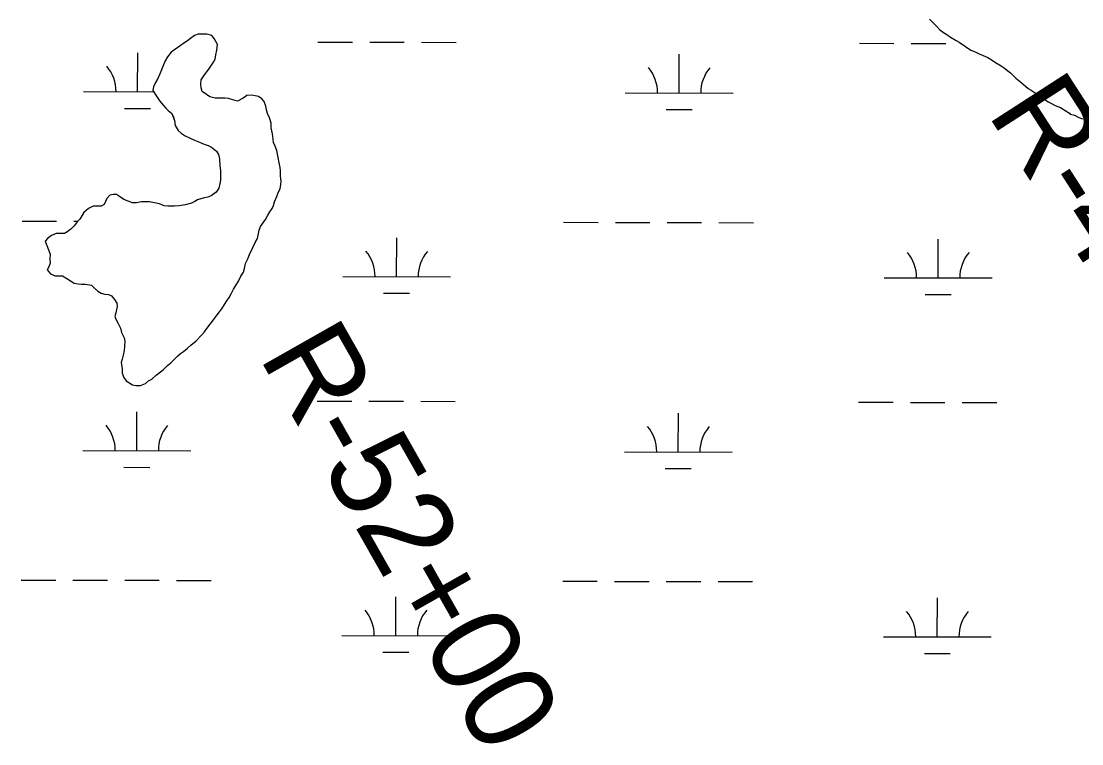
# Model space of a CAD drawing. Extents: x 3180038 to 3217926, y 922069 to 947485.
# Drawn here: x 3193033 to 3194016, y 935833 to 936503 of the extents above; entities that cross this region are included whole.
import ezdxf

# ---------------------------------------------------------------- set-up
doc = ezdxf.new("R2010")
doc.units = 0
for name, color, linetype in [('V-RIVR-RANG-IDEN', 7, 'Continuous'), ('V-SITE-VEGE', 7, 'Continuous'), ('V-TOPO-SHOR', 7, 'Continuous'), ('V-WETL-SWMP', 7, 'Continuous')]:
    doc.layers.add(name, color=color, linetype=linetype)

msp = doc.modelspace()

# ---------------------------------------------------------------- linework, layer by layer
at = {"layer": 'V-SITE-VEGE'}
for points in [[(3193875.23, 936504.62), (3193877.99, 936501.92), (3193881.45, 936498.55), (3193884.91, 936494.83), (3193888.35, 936492.49), (3193891.45, 936490.48), (3193894.9, 936488.13), (3193900.06, 936485.12), (3193902.81, 936483.44), (3193908.67, 936479.42), (3193913.49, 936476.06)], [(3193273.45, 936367.39), (3193272.71, 936371.47), (3193271.63, 936376.58), (3193270.52, 936383.06), (3193268.76, 936387.13), (3193267.35, 936390.53), (3193266.97, 936393.6), (3193266.23, 936398.37), (3193265.14, 936404.17), (3193265.09, 936408.26), (3193263.66, 936413.37), (3193261.9, 936417.44), (3193260.83, 936420.85), (3193260.11, 936424.25), (3193258.69, 936428.33), (3193256.61, 936431.04), (3193253.51, 936433.05), (3193250.43, 936433.7), (3193247, 936434.34), (3193242.57, 936433.94), (3193239.18, 936431.51), (3193234.09, 936428.71), (3193229.64, 936430.02), (3193225.52, 936431.34), (3193222.45, 936431.64), (3193217.32, 936431.58), (3193213.23, 936431.53), (3193208.43, 936432.84), (3193205.33, 936434.84), (3193201.19, 936437.87), (3193200.13, 936441.27), (3193200.09, 936444.34), (3193200.38, 936448.45), (3193203.39, 936453.26), (3193207.43, 936458.44), (3193209.1, 936461.19), (3193211.79, 936464.98), (3193213.12, 936467.73), (3193213.75, 936471.84), (3193214.73, 936475.95), (3193215.34, 936481.42), (3193213.94, 936484.13), (3193212.2, 936486.85), (3193210.12, 936489.55), (3193205.66, 936490.86), (3193201.56, 936490.81), (3193197.47, 936490.76), (3193194.06, 936489.69), (3193190.34, 936486.91), (3193187.64, 936484.83), (3193184.25, 936482.4), (3193180.86, 936479.97), (3193175.44, 936476.48), (3193172.4, 936474.06), (3193169.03, 936469.91), (3193167.03, 936466.13), (3193164.71, 936460.98), (3193162.39, 936454.81), (3193160.06, 936449.65), (3193158.06, 936446.21), (3193156.06, 936442.09), (3193155.42, 936438.67), (3193158.9, 936433.25), (3193162.03, 936428.85), (3193165.5, 936424.79), (3193167.57, 936422.43), (3193169.66, 936420.06), (3193172.75, 936417.71), (3193174.15, 936414.99), (3193175.57, 936410.91), (3193176.32, 936406.14), (3193179.1, 936401.73), (3193181.87, 936399.04), (3193185.31, 936396.69), (3193189.43, 936394.69), (3193194.24, 936392.7), (3193198.7, 936390.71), (3193203.16, 936389.06), (3193206.6, 936387.73), (3193209.69, 936386.06), (3193214.52, 936382.36), (3193216.26, 936379.31), (3193217.34, 936375.23), (3193217.42, 936368.74), (3193218.15, 936364.65), (3193218.21, 936360.21), (3193218.27, 936355.43), (3193217.62, 936352.35), (3193216.65, 936348.24), (3193214.3, 936344.45), (3193209.57, 936340.98), (3193206.5, 936339.92), (3193203.1, 936339.19), (3193196.97, 936337.41), (3193194.26, 936335.67), (3193191.21, 936334.26), (3193185.42, 936332.82), (3193179.97, 936331.73), (3193175.53, 936331.33), (3193169.38, 936331.6), (3193165.96, 936331.9)], [(3193913.49, 936476.06), (3193917.61, 936474.41), (3193921.39, 936472.74), (3193925.16, 936471.08), (3193929.29, 936469.09), (3193933.41, 936466.75), (3193936.51, 936464.74), (3193941.68, 936461.38), (3193944.43, 936459.71), (3193947.88, 936457.02), (3193950.3, 936455), (3193952.71, 936452.98), (3193955.48, 936449.94), (3193959.97, 936446.24), (3193964.45, 936442.54), (3193966.87, 936440.52), (3193969.62, 936438.85), (3193974.1, 936435.83), (3193979.95, 936431.81), (3193985.46, 936428.12), (3193988.9, 936426.45), (3193991.65, 936424.78), (3193996.8, 936422.79), (3194000.93, 936420.11), (3194005.06, 936417.77), (3194005.76, 936416.75), (3194009.86, 936415.78), (3194013.65, 936413.78), (3194017.08, 936412.46)], [(3193060.31, 936286.87), (3193060.02, 936282.77), (3193060.41, 936278.68), (3193059.08, 936275.25), (3193057.41, 936272.5), (3193060.53, 936268.78), (3193064.99, 936266.78), (3193068.07, 936266.82), (3193071.82, 936266.87), (3193075.61, 936264.52), (3193079.05, 936262.18), (3193082.49, 936260.17), (3193086.26, 936259.53), (3193089.34, 936259.23), (3193092.75, 936259.27), (3193098.57, 936258.32), (3193101.34, 936255.62), (3193104.45, 936252.59), (3193107.54, 936250.92), (3193110.97, 936249.93), (3193114.39, 936249.64), (3193117.14, 936248.3), (3193119.91, 936244.92), (3193122, 936241.53), (3193122.38, 936238.46), (3193121.09, 936232.64), (3193120.1, 936229.22), (3193121.51, 936226.16), (3193122.91, 936223.44), (3193125.36, 936218.35), (3193126.44, 936214.27), (3193128.89, 936209.52), (3193129.61, 936206.45), (3193129.33, 936201.33), (3193129.04, 936197.56), (3193128.06, 936193.45), (3193127.08, 936189.68), (3193126.1, 936186.6), (3193127.19, 936180.81), (3193126.9, 936176.7), (3193128.66, 936172.63), (3193130.75, 936169.58), (3193136.6, 936165.9), (3193139.68, 936165.25), (3193144.12, 936165.31), (3193148.54, 936167.07), (3193151.58, 936169.5), (3193154.63, 936171.24), (3193158.69, 936174.71), (3193161.39, 936177.13), (3193165.11, 936179.91), (3193169.17, 936183.72), (3193172.21, 936186.14), (3193175.24, 936189.26), (3193178.62, 936192.71), (3193180.98, 936194.79), (3193184.03, 936196.88), (3193187.75, 936200), (3193190.79, 936202.77), (3193195.52, 936206.58), (3193200.92, 936212.12), (3193203.27, 936214.88), (3193205.63, 936217.98), (3193208.65, 936222.11), (3193211.67, 936226.25), (3193213.69, 936228.67), (3193216.04, 936232.11), (3193219.4, 936236.25), (3193221.74, 936240.38), (3193224.09, 936243.82), (3193226.1, 936246.92), (3193228.11, 936250.36), (3193230.11, 936254.49), (3193232.45, 936257.93), (3193234.79, 936262.05), (3193237.13, 936266.53), (3193239.47, 936270.31), (3193240.45, 936273.74), (3193241.42, 936278.19), (3193243.42, 936282.65), (3193245.07, 936286.77), (3193248.07, 936293.3), (3193250.4, 936297.77), (3193252.4, 936301.55), (3193253.37, 936306), (3193254.02, 936309.09), (3193255.34, 936312.52), (3193260.04, 936319.06), (3193261.71, 936322.5), (3193264.05, 936326.28), (3193266.06, 936329.38), (3193267.39, 936332.13), (3193268.38, 936335.56), (3193270.37, 936340.36), (3193272.02, 936344.82), (3193273.35, 936347.58), (3193273.98, 936351.68), (3193274.29, 936354.76), (3193273.89, 936359.19), (3193273.83, 936364.32), (3193273.45, 936367.39)], [(3193165.96, 936331.9), (3193161.5, 936333.55), (3193155.34, 936334.84), (3193152.26, 936335.49), (3193149.19, 936335.45), (3193145.09, 936335.4), (3193140.31, 936334.66), (3193136.56, 936334.61), (3193128.67, 936337.59), (3193124.53, 936340.27), (3193121.78, 936342.28), (3193118.71, 936342.25), (3193115.64, 936341.52), (3193112.95, 936338.42), (3193111.61, 936335.67), (3193110.28, 936332.92), (3193107.57, 936331.52), (3193103.13, 936331.46), (3193100.05, 936331.42), (3193095.98, 936329.33), (3193091.59, 936325.52), (3193089.58, 936322.42), (3193087.91, 936319.32), (3193085.21, 936316.9), (3193082.52, 936313.11), (3193079.82, 936310.34), (3193076.78, 936307.91), (3193073.73, 936306.17), (3193071.68, 936306.14), (3193069.97, 936306.12), (3193065.87, 936306.07), (3193061.46, 936304.31), (3193057.73, 936301.53), (3193056.05, 936299.46), (3193055.71, 936299.11), (3193060.31, 936286.87)]]:
    msp.add_lwpolyline(points, dxfattribs=at)
at = {"layer": 'V-TOPO-SHOR'}
for points in [[(3193875.23, 936504.62), (3193877.99, 936501.92), (3193881.45, 936498.55), (3193884.91, 936494.83), (3193888.35, 936492.49), (3193891.45, 936490.48), (3193894.9, 936488.13), (3193900.06, 936485.12), (3193902.81, 936483.44), (3193908.67, 936479.42), (3193913.49, 936476.06), (3193917.61, 936474.41), (3193921.39, 936472.74), (3193925.16, 936471.08), (3193929.29, 936469.09), (3193933.41, 936466.75), (3193936.51, 936464.74), (3193941.68, 936461.38), (3193944.43, 936459.71), (3193947.88, 936457.02), (3193950.3, 936455), (3193952.71, 936452.98), (3193955.48, 936449.94), (3193959.97, 936446.24), (3193964.45, 936442.54), (3193966.87, 936440.52), (3193969.62, 936438.85), (3193974.1, 936435.83), (3193979.95, 936431.81), (3193985.46, 936428.12), (3193988.9, 936426.45), (3193991.65, 936424.78), (3193996.8, 936422.79), (3194000.93, 936420.11), (3194005.06, 936417.77), (3194005.76, 936416.75), (3194009.86, 936415.78), (3194013.65, 936413.78), (3194017.08, 936412.46)], [(3193273.45, 936367.39), (3193272.71, 936371.47), (3193271.63, 936376.58), (3193270.52, 936383.06), (3193268.76, 936387.13), (3193267.35, 936390.53), (3193266.97, 936393.6), (3193266.23, 936398.37), (3193265.14, 936404.17), (3193265.09, 936408.26), (3193263.66, 936413.37), (3193261.9, 936417.44), (3193260.83, 936420.85), (3193260.11, 936424.25), (3193258.69, 936428.33), (3193256.61, 936431.04), (3193253.51, 936433.05), (3193250.43, 936433.7), (3193247, 936434.34), (3193242.57, 936433.94), (3193239.18, 936431.51), (3193234.09, 936428.71), (3193229.64, 936430.02), (3193225.52, 936431.34), (3193222.45, 936431.64), (3193217.32, 936431.58), (3193213.23, 936431.53), (3193208.43, 936432.84), (3193205.33, 936434.84), (3193201.19, 936437.87), (3193200.13, 936441.27), (3193200.09, 936444.34), (3193200.38, 936448.45), (3193203.39, 936453.26), (3193207.43, 936458.44), (3193209.1, 936461.19), (3193211.79, 936464.98), (3193213.12, 936467.73), (3193213.75, 936471.84), (3193214.73, 936475.95), (3193215.34, 936481.42), (3193213.94, 936484.13), (3193212.2, 936486.84), (3193210.12, 936489.55), (3193205.66, 936490.86), (3193201.56, 936490.81), (3193197.47, 936490.76), (3193194.06, 936489.69), (3193190.34, 936486.91), (3193187.63, 936484.83), (3193184.25, 936482.4), (3193180.86, 936479.97), (3193175.44, 936476.48), (3193172.4, 936474.06), (3193169.03, 936469.91), (3193167.03, 936466.13), (3193164.71, 936460.98), (3193162.39, 936454.81), (3193160.06, 936449.65), (3193158.06, 936446.21), (3193156.06, 936442.09), (3193155.42, 936438.67), (3193158.9, 936433.25), (3193162.03, 936428.85), (3193165.5, 936424.79), (3193167.57, 936422.43), (3193169.65, 936420.06), (3193172.76, 936417.71), (3193174.15, 936414.99), (3193175.57, 936410.91), (3193176.32, 936406.14), (3193179.1, 936401.73), (3193181.87, 936399.04), (3193185.31, 936396.69), (3193189.43, 936394.69), (3193194.24, 936392.7), (3193198.7, 936390.71), (3193203.16, 936389.06), (3193206.6, 936387.73), (3193209.69, 936386.06), (3193214.52, 936382.36), (3193216.26, 936379.31), (3193217.34, 936375.23), (3193217.42, 936368.74), (3193218.15, 936364.65), (3193218.21, 936360.21), (3193218.27, 936355.43), (3193217.62, 936352.35), (3193216.65, 936348.24), (3193214.3, 936344.45), (3193209.57, 936340.98), (3193206.5, 936339.92), (3193203.1, 936339.19), (3193196.97, 936337.41), (3193194.26, 936335.67), (3193191.21, 936334.26), (3193185.42, 936332.82), (3193179.97, 936331.73), (3193175.53, 936331.33), (3193169.38, 936331.6), (3193165.96, 936331.9)], [(3193060.31, 936286.87), (3193060.02, 936282.77), (3193060.41, 936278.68), (3193059.08, 936275.25), (3193057.41, 936272.5), (3193060.53, 936268.78), (3193064.99, 936266.78), (3193068.07, 936266.82), (3193071.82, 936266.87), (3193075.61, 936264.52), (3193079.05, 936262.18), (3193082.49, 936260.17), (3193086.26, 936259.53), (3193089.34, 936259.23), (3193092.75, 936259.27), (3193098.57, 936258.32), (3193101.33, 936255.62), (3193104.45, 936252.59), (3193107.54, 936250.92), (3193110.97, 936249.93), (3193114.39, 936249.64), (3193117.14, 936248.3), (3193119.91, 936244.92), (3193122, 936241.53), (3193122.38, 936238.46), (3193121.09, 936232.64), (3193120.1, 936229.22), (3193121.51, 936226.16), (3193122.91, 936223.44), (3193125.36, 936218.35), (3193126.44, 936214.27), (3193128.89, 936209.52), (3193129.61, 936206.45), (3193129.33, 936201.33), (3193129.04, 936197.56), (3193128.06, 936193.45), (3193127.08, 936189.68), (3193126.1, 936186.6), (3193127.19, 936180.81), (3193126.9, 936176.7), (3193128.66, 936172.63), (3193130.75, 936169.58), (3193136.6, 936165.9), (3193139.68, 936165.25), (3193144.12, 936165.31), (3193148.54, 936167.07), (3193151.58, 936169.5), (3193154.63, 936171.24), (3193158.69, 936174.71), (3193161.39, 936177.13), (3193165.11, 936179.91), (3193169.17, 936183.72), (3193172.21, 936186.14), (3193175.24, 936189.26), (3193178.62, 936192.71), (3193180.98, 936194.79), (3193184.03, 936196.88), (3193187.75, 936200), (3193190.79, 936202.77), (3193195.52, 936206.58), (3193200.92, 936212.12), (3193203.27, 936214.88), (3193205.63, 936217.98), (3193208.65, 936222.11), (3193211.67, 936226.25), (3193213.69, 936228.67), (3193216.04, 936232.11), (3193219.4, 936236.25), (3193221.74, 936240.38), (3193224.09, 936243.82), (3193226.1, 936246.92), (3193228.11, 936250.36), (3193230.11, 936254.49), (3193232.45, 936257.93), (3193234.79, 936262.06), (3193237.13, 936266.53), (3193239.47, 936270.31), (3193240.45, 936273.74), (3193241.42, 936278.19), (3193243.42, 936282.65), (3193245.07, 936286.77), (3193248.07, 936293.3), (3193250.4, 936297.77), (3193252.4, 936301.55), (3193253.37, 936306), (3193254.02, 936309.08), (3193255.34, 936312.52), (3193260.04, 936319.06), (3193261.71, 936322.5), (3193264.05, 936326.28), (3193266.06, 936329.38), (3193267.39, 936332.13), (3193268.38, 936335.56), (3193270.37, 936340.37), (3193272.02, 936344.82), (3193273.35, 936347.58), (3193273.98, 936351.68), (3193274.29, 936354.76), (3193273.89, 936359.19), (3193273.83, 936364.32), (3193273.45, 936367.39)], [(3193165.96, 936331.9), (3193161.5, 936333.55), (3193155.34, 936334.84), (3193152.26, 936335.49), (3193149.19, 936335.45), (3193145.09, 936335.4), (3193140.31, 936334.66), (3193136.56, 936334.61), (3193128.67, 936337.59), (3193124.53, 936340.27), (3193121.78, 936342.28), (3193118.71, 936342.24), (3193115.64, 936341.52), (3193112.95, 936338.42), (3193111.61, 936335.67), (3193110.28, 936332.92), (3193107.57, 936331.52), (3193103.13, 936331.46), (3193100.05, 936331.42), (3193095.98, 936329.33), (3193091.59, 936325.51), (3193089.58, 936322.42), (3193087.91, 936319.32), (3193085.21, 936316.9), (3193082.52, 936313.11), (3193079.82, 936310.34), (3193076.78, 936307.91), (3193073.73, 936306.17), (3193071.68, 936306.14), (3193069.97, 936306.12), (3193065.87, 936306.07), (3193061.46, 936304.31), (3193057.73, 936301.53), (3193056.05, 936299.46), (3193055.71, 936299.11), (3193060.31, 936286.87)]]:
    msp.add_lwpolyline(points, dxfattribs=at)
at = {"layer": 'V-WETL-SWMP'}
for p, q in [((3193308.51, 936483.55), (3193340.51, 936483.47)), ((3193356.51, 936483.44), (3193388.51, 936483.37)), ((3193404.51, 936483.33), (3193436.51, 936483.26)), ((3193810.42, 936482.41), (3193842.42, 936482.34)), ((3193858.42, 936482.31), (3193890.42, 936482.23)), ((3193141.35, 936437.49), (3193141.43, 936473.49)), ((3193643.25, 936436.36), (3193643.33, 936472.36)), ((3193091.35, 936437.61), (3193156.19, 936437.46)), ((3193593.25, 936436.48), (3193693.25, 936436.25)), ((3193129.31, 936422.09), (3193153.31, 936422.04)), ((3193631.22, 936420.96), (3193655.22, 936420.91)), ((3193034.23, 936317.67), (3193066.23, 936317.6)), ((3193082.23, 936317.56), (3193085.94, 936317.55)), ((3193536.14, 936316.54), (3193568.14, 936316.46)), ((3193584.14, 936316.43), (3193616.14, 936316.36)), ((3193632.13, 936316.32), (3193664.13, 936316.25)), ((3193680.13, 936316.21), (3193712.13, 936316.14)), ((3193381.43, 936266.15), (3193381.51, 936302.14)), ((3193883.33, 936265.01), (3193883.42, 936301.01)), ((3193331.43, 936266.26), (3193431.43, 936266.03)), ((3193833.33, 936265.13), (3193933.33, 936264.9)), ((3193369.39, 936250.74), (3193393.39, 936250.69)), ((3193871.3, 936249.61), (3193895.3, 936249.56)), ((3193307.76, 936150.88), (3193339.76, 936150.81)), ((3193355.76, 936150.77), (3193387.76, 936150.7)), ((3193403.76, 936150.67), (3193435.76, 936150.59)), ((3193809.66, 936149.75), (3193841.66, 936149.68)), ((3193857.66, 936149.64), (3193889.66, 936149.57)), ((3193140.59, 936104.83), (3193140.67, 936140.83)), ((3193905.66, 936149.53), (3193937.66, 936149.46)), ((3193642.5, 936103.7), (3193642.58, 936139.7)), ((3193090.59, 936104.94), (3193190.59, 936104.72)), ((3193592.5, 936103.81), (3193692.5, 936103.59)), ((3193128.56, 936089.43), (3193152.56, 936089.37)), ((3193630.46, 936088.3), (3193654.46, 936088.24)), ((3193033.47, 935985.01), (3193065.47, 935984.93)), ((3193081.47, 935984.9), (3193113.47, 935984.83)), ((3193129.47, 935984.79), (3193161.47, 935984.72)), ((3193177.47, 935984.68), (3193209.47, 935984.61)), ((3193535.38, 935983.87), (3193567.38, 935983.8)), ((3193583.38, 935983.77), (3193615.38, 935983.69)), ((3193631.38, 935983.66), (3193663.38, 935983.59)), ((3193679.38, 935983.55), (3193711.38, 935983.48)), ((3193380.67, 935933.48), (3193380.75, 935969.48)), ((3193882.58, 935932.35), (3193882.66, 935968.35)), ((3193330.67, 935933.59), (3193430.67, 935933.37)), ((3193832.58, 935932.46), (3193932.58, 935932.24)), ((3193368.64, 935918.08), (3193392.64, 935918.02)), ((3193870.54, 935916.95), (3193894.54, 935916.89))]:
    msp.add_line(p, q, dxfattribs=at)
for points in [[(3193875.23, 936504.62), (3193877.99, 936501.92), (3193881.45, 936498.55), (3193884.91, 936494.83), (3193888.35, 936492.49), (3193891.45, 936490.48), (3193894.9, 936488.13), (3193900.06, 936485.12), (3193902.81, 936483.44), (3193908.67, 936479.42), (3193913.49, 936476.06), (3193917.61, 936474.41), (3193921.39, 936472.75), (3193925.16, 936471.08), (3193929.29, 936469.09), (3193933.41, 936466.75), (3193936.51, 936464.74), (3193941.68, 936461.39), (3193944.43, 936459.71), (3193947.88, 936457.02), (3193950.29, 936455), (3193952.71, 936452.98), (3193955.48, 936449.94), (3193959.97, 936446.24), (3193964.45, 936442.54), (3193966.87, 936440.52), (3193969.62, 936438.85), (3193974.1, 936435.83), (3193979.95, 936431.8), (3193985.46, 936428.12), (3193988.9, 936426.45), (3193991.65, 936424.78), (3193996.8, 936422.79), (3194000.93, 936420.11), (3194005.06, 936417.77), (3194005.75, 936416.76), (3194009.86, 936415.78), (3194013.65, 936413.78), (3194017.08, 936412.46)], [(3193273.45, 936367.38), (3193272.71, 936371.47), (3193271.63, 936376.58), (3193270.52, 936383.06), (3193268.76, 936387.13), (3193267.35, 936390.53), (3193266.97, 936393.6), (3193266.23, 936398.37), (3193265.14, 936404.17), (3193265.09, 936408.26), (3193263.66, 936413.37), (3193261.9, 936417.45), (3193260.83, 936420.85), (3193260.11, 936424.25), (3193258.69, 936428.33), (3193256.61, 936431.04), (3193253.51, 936433.05), (3193250.43, 936433.7), (3193247, 936434.34), (3193242.57, 936433.94), (3193239.18, 936431.51), (3193234.09, 936428.71), (3193229.64, 936430.02), (3193225.52, 936431.34), (3193222.45, 936431.64), (3193217.32, 936431.58), (3193213.23, 936431.53), (3193208.43, 936432.84), (3193205.33, 936434.85), (3193201.19, 936437.87), (3193200.13, 936441.27), (3193200.09, 936444.34), (3193200.38, 936448.45), (3193203.39, 936453.26), (3193207.43, 936458.44), (3193209.1, 936461.19), (3193211.79, 936464.98), (3193213.12, 936467.73), (3193213.75, 936471.84), (3193214.73, 936475.95), (3193215.34, 936481.42), (3193213.94, 936484.13), (3193212.2, 936486.84), (3193210.12, 936489.55), (3193205.66, 936490.86), (3193201.56, 936490.81), (3193197.47, 936490.76), (3193194.06, 936489.69), (3193190.34, 936486.91), (3193187.63, 936484.83), (3193184.25, 936482.4), (3193180.86, 936479.97), (3193175.44, 936476.48), (3193172.4, 936474.06), (3193169.04, 936469.92), (3193167.03, 936466.13), (3193164.71, 936460.98), (3193162.39, 936454.81), (3193160.06, 936449.65), (3193158.06, 936446.21), (3193156.06, 936442.09), (3193155.42, 936438.67), (3193158.9, 936433.25), (3193162.03, 936428.85), (3193165.5, 936424.79), (3193167.57, 936422.42), (3193169.65, 936420.06), (3193172.76, 936417.71), (3193174.16, 936414.99), (3193175.57, 936410.91), (3193176.31, 936406.14), (3193179.1, 936401.73), (3193181.87, 936399.04), (3193185.31, 936396.69), (3193189.43, 936394.69), (3193194.24, 936392.7), (3193198.7, 936390.71), (3193203.17, 936389.05), (3193206.6, 936387.73), (3193209.69, 936386.06), (3193214.52, 936382.36), (3193216.26, 936379.31), (3193217.34, 936375.23), (3193217.42, 936368.74), (3193218.15, 936364.65), (3193218.21, 936360.21), (3193218.27, 936355.43), (3193217.62, 936352.35), (3193216.65, 936348.24), (3193214.3, 936344.45), (3193209.57, 936340.98), (3193206.51, 936339.92), (3193203.1, 936339.19), (3193196.97, 936337.41), (3193194.26, 936335.67), (3193191.21, 936334.26), (3193185.42, 936332.82), (3193179.97, 936331.73), (3193175.53, 936331.34), (3193169.38, 936331.6), (3193165.96, 936331.9)], [(3193213.69, 936228.67), (3193216.04, 936232.11), (3193219.4, 936236.25), (3193221.74, 936240.38), (3193224.09, 936243.82), (3193226.1, 936246.92), (3193228.11, 936250.36), (3193230.11, 936254.48), (3193232.45, 936257.93), (3193234.79, 936262.06), (3193237.13, 936266.53), (3193239.47, 936270.31), (3193240.45, 936273.74), (3193241.42, 936278.19), (3193243.42, 936282.65), (3193245.07, 936286.77), (3193248.07, 936293.3), (3193250.4, 936297.77), (3193252.4, 936301.55), (3193253.37, 936306), (3193254.02, 936309.08), (3193255.34, 936312.52), (3193260.04, 936319.06), (3193261.71, 936322.5), (3193264.05, 936326.28), (3193266.06, 936329.38), (3193267.39, 936332.13), (3193268.38, 936335.56), (3193270.37, 936340.37), (3193272.02, 936344.83), (3193273.35, 936347.57), (3193273.98, 936351.68), (3193274.29, 936354.76), (3193273.89, 936359.19), (3193273.83, 936364.32), (3193273.45, 936367.38)], [(3193165.96, 936331.9), (3193161.5, 936333.55), (3193155.34, 936334.84), (3193152.26, 936335.49), (3193149.18, 936335.45), (3193145.09, 936335.4), (3193140.31, 936334.66), (3193136.56, 936334.61), (3193128.67, 936337.59), (3193124.53, 936340.27), (3193121.78, 936342.28), (3193118.7, 936342.24), (3193115.64, 936341.52), (3193112.95, 936338.42), (3193111.61, 936335.67), (3193110.28, 936332.92), (3193107.57, 936331.52), (3193103.13, 936331.46), (3193100.05, 936331.43), (3193095.98, 936329.33), (3193091.59, 936325.51), (3193089.58, 936322.42), (3193087.91, 936319.32), (3193085.21, 936316.9), (3193082.52, 936313.11), (3193079.82, 936310.34), (3193076.78, 936307.91), (3193073.73, 936306.17), (3193071.68, 936306.14), (3193069.97, 936306.12), (3193065.87, 936306.07), (3193061.46, 936304.31), (3193057.73, 936301.53), (3193056.05, 936299.46), (3193055.71, 936299.11), (3193060.31, 936286.88), (3193060.02, 936282.77), (3193060.41, 936278.68), (3193059.08, 936275.25), (3193057.41, 936272.5), (3193060.53, 936268.78), (3193064.99, 936266.78), (3193068.07, 936266.82), (3193071.82, 936266.87), (3193075.61, 936264.52), (3193079.05, 936262.18), (3193082.49, 936260.17), (3193086.26, 936259.53), (3193089.34, 936259.23), (3193092.75, 936259.27), (3193098.57, 936258.32), (3193101.33, 936255.62), (3193104.45, 936252.59), (3193107.54, 936250.92), (3193110.97, 936249.94), (3193114.39, 936249.64), (3193117.14, 936248.3), (3193119.91, 936244.92), (3193122, 936241.53), (3193122.38, 936238.46), (3193121.09, 936232.64), (3193120.1, 936229.22), (3193121.51, 936226.16), (3193122.91, 936223.44), (3193125.36, 936218.35), (3193126.44, 936214.27), (3193128.89, 936209.52), (3193129.61, 936206.45), (3193129.33, 936201.32), (3193129.03, 936197.56), (3193128.06, 936193.45), (3193127.08, 936189.68), (3193126.1, 936186.6), (3193127.19, 936180.81), (3193126.9, 936176.7), (3193128.66, 936172.63), (3193130.75, 936169.58), (3193136.6, 936165.9), (3193139.68, 936165.25), (3193144.12, 936165.31), (3193148.54, 936167.07), (3193151.58, 936169.5), (3193154.63, 936171.24), (3193158.69, 936174.71), (3193161.39, 936177.13), (3193165.11, 936179.91), (3193169.17, 936183.72), (3193172.21, 936186.14), (3193175.24, 936189.26), (3193178.62, 936192.71), (3193180.98, 936194.79), (3193184.03, 936196.88), (3193187.75, 936200), (3193190.79, 936202.77), (3193195.52, 936206.58), (3193200.92, 936212.12), (3193203.27, 936214.88), (3193205.63, 936217.98), (3193208.65, 936222.12), (3193211.67, 936226.25), (3193213.69, 936228.67)]]:
    msp.add_lwpolyline(points, dxfattribs=at)
for centre, start, end in [((3193086.1, 936438.09), 359.09904, 40.6427), ((3193588.01, 936436.96), 359.09904, 40.6427), ((3193698.5, 936436.71), 139.09899, 180.64264), ((3193326.19, 936266.74), 359.09904, 40.6427), ((3193436.67, 936266.5), 139.09899, 180.64264), ((3193828.09, 936265.61), 359.09904, 40.6427), ((3193938.58, 936265.36), 139.09899, 180.64264), ((3193085.35, 936105.43), 359.09904, 40.6427), ((3193195.83, 936105.18), 139.09899, 180.64264), ((3193587.25, 936104.3), 359.09904, 40.6427), ((3193697.74, 936104.05), 139.09899, 180.64264), ((3193325.43, 935934.08), 359.09904, 40.6427), ((3193435.92, 935933.83), 139.09899, 180.64264), ((3193827.34, 935932.95), 359.09904, 40.6427), ((3193937.82, 935932.7), 139.09899, 180.64264)]:
    msp.add_arc(centre, 35.25, start, end, dxfattribs=at)

# ---------------------------------------------------------------- texts
at = {"layer": 'V-RIVR-RANG-IDEN'}
for s, rotation, p in [('R-43+00', 302.82272, (3193928.14, 936417.74)), ('R-52+00', 299.55429, (3193253.21, 936192.28))]:
    msp.add_text(s, height=83, rotation=rotation, dxfattribs=at).set_placement(p)

doc.saveas('drawing.dxf')
